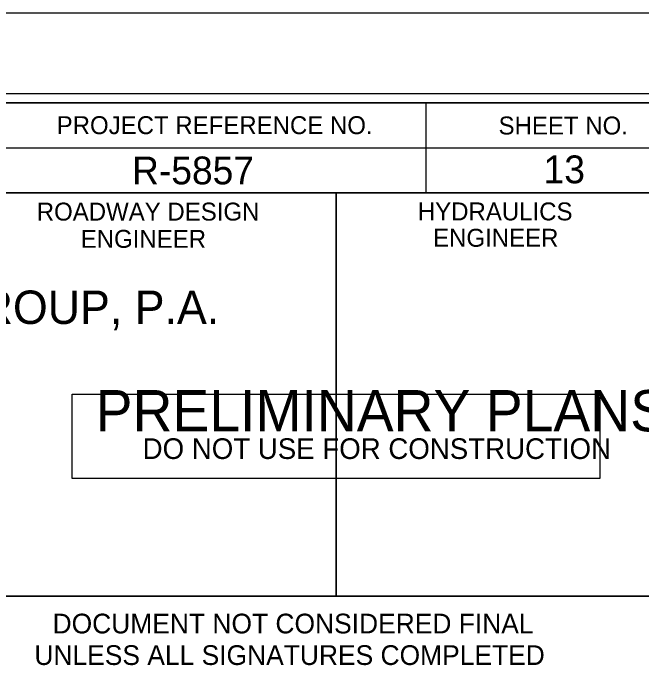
# Model space of a CAD drawing. Extents: x 2186391 to 2188300, y 74582 to 75682.
# Drawn here: x 2187867.8 to 2188042.9, y 75496.8 to 75682.3 of the extents above; entities that cross this region are included whole.
import ezdxf

# ---------------------------------------------------------------- set-up
doc = ezdxf.new("R2010")
doc.units = 0
for name, color, linetype in [('Exist Structure Minor Culvert Topo Terminator', 7, 'Continuous'), ('Exist Structure Minor Footbridge', 7, 'Continuous'), ('Scratch_Level_0', 7, 'Continuous'), ('Sheet Cutting Line CELL', 7, 'Continuous'), ('Sheet Data Field CELL', 7, 'Continuous'), ('Sheet Plan CELL', 7, 'Continuous'), ('Sheet Sticker Exception Certification CELL', 7, 'Continuous'), ('Sheet Sticker Incomplete CELL', 7, 'Continuous'), ('Sheet Sticker Preliminary CELL', 7, 'Continuous')]:
    doc.layers.add(name, color=color, linetype=linetype)

msp = doc.modelspace()

# ---------------------------------------------------------------- linework, layer by layer
at = {"layer": 'Exist Structure Minor Footbridge'}
msp.add_lwpolyline([(2187884.21, 75552.57), (2187884.21, 75576.07), (2188031.21, 75576.07), (2188031.21, 75552.57)], close=True, dxfattribs=at)
at = {"layer": 'Scratch_Level_0'}
msp.add_line((2188074.69, 75682.28), (2186390.69, 75682.28), dxfattribs=at)
at = {"layer": 'Sheet Cutting Line CELL'}
for p, q in [((2187982.69, 75657.23), (2187982.69, 75632.23)), ((2187857.64, 75644.73), (2188057.69, 75644.73)), ((2187957.69, 75632.23), (2187957.69, 75519.78))]:
    msp.add_line(p, q, dxfattribs=at)
for points in [[(2188057.69, 75657.28), (2186557.69, 75657.28), (2186557.69, 74607.28), (2188057.69, 74607.28)], [(2187857.64, 75657.28), (2188057.69, 75657.28), (2188057.69, 75632.23), (2187857.64, 75632.23)], [(2187857.64, 75632.23), (2187957.69, 75632.23), (2187957.69, 75519.73), (2187857.64, 75519.73)], [(2187957.69, 75632.23), (2188057.69, 75632.23), (2188057.69, 75519.73), (2187957.69, 75519.73)]]:
    msp.add_lwpolyline(points, close=True, dxfattribs=at)
at = {"layer": 'Sheet Data Field CELL'}
msp.add_line((2187857.64, 75519.73), (2188057.68, 75519.73), dxfattribs=at)
msp.add_line((2187857.64, 75519.73), (2188057.68, 75519.73), dxfattribs=at)
at = {"layer": 'Sheet Sticker Exception Certification CELL'}
msp.add_lwpolyline([(2187507.69, 75157.28), (2187557.69, 75157.28), (2187557.69, 75657.28), (2187607.69, 75657.28), (2187607.69, 75157.28), (2187657.69, 75157.28), (2187657.69, 75657.28), (2187707.69, 75657.28), (2187707.69, 75157.28), (2187757.69, 75157.28), (2187757.69, 75657.28), (2187807.69, 75657.28), (2187807.69, 75157.28), (2187857.69, 75157.28), (2187857.69, 75657.28), (2187883.99, 75657.28)], dxfattribs=at)
at = {"layer": 'Sheet Sticker Incomplete CELL'}
msp.add_lwpolyline([(2186390.69, 74582.28), (2188074.69, 74582.28), (2188074.69, 75682.28), (2186390.69, 75682.28)], close=True, dxfattribs=at)
at = {"layer": 'Sheet Sticker Preliminary CELL'}
msp.add_lwpolyline([(2186403.69, 74604.73), (2188070.19, 74604.73), (2188070.19, 75659.83), (2186403.69, 75659.83)], close=True, dxfattribs=at)

# ---------------------------------------------------------------- texts
at = {"layer": 'Exist Structure Minor Culvert Topo Terminator'}
msp.add_text('SUNGATE DESIGN GROUP, P.A.', height=9.3194, dxfattribs=at).set_placement((2187734.03, 75595.66))
at = {"layer": 'Exist Structure Minor Footbridge'}
for s, height, p in [('PRELIMINARY PLANS', 11.52, (2187890.71, 75565.72)), ('DO NOT USE FOR CONSTRUCTION', 5.76, (2187903.81, 75558.02))]:
    msp.add_text(s, height=height, dxfattribs=at).set_placement(p)
at = {"layer": 'Sheet Cutting Line CELL'}
for s, height, p in [('PROJECT REFERENCE NO.', 5.0001, (2187879.85, 75648.59)), ('SHEET NO.', 5, (2188003, 75648.49)), ('ROADWAY DESIGN', 5.0001, (2187874.3, 75624.49)), ('HYDRAULICS', 5, (2187980.5, 75624.54)), ('ENGINEER', 5, (2187886.55, 75616.89)), ('ENGINEER', 5, (2187984.75, 75617.19))]:
    msp.add_text(s, height=height, dxfattribs=at).set_placement(p)
at = {"layer": 'Sheet Data Field CELL'}
for s, p in [('DOCUMENT NOT CONSIDERED FINAL', (2187878.71, 75509.38)), ('DOCUMENT NOT CONSIDERED FINAL', (2187878.71, 75509.38)), ('UNLESS ALL SIGNATURES COMPLETED', (2187873.64, 75500.58)), ('UNLESS ALL SIGNATURES COMPLETED', (2187873.64, 75500.58))]:
    msp.add_text(s, height=5.5, dxfattribs=at).set_placement(p)
at = {"layer": 'Sheet Plan CELL'}
for s, p in [('R-5857', (2187900.85, 75634.59)), ('13', (2188015.53, 75634.89))]:
    msp.add_text(s, height=7.75, dxfattribs=at).set_placement(p)

doc.saveas('drawing.dxf')
